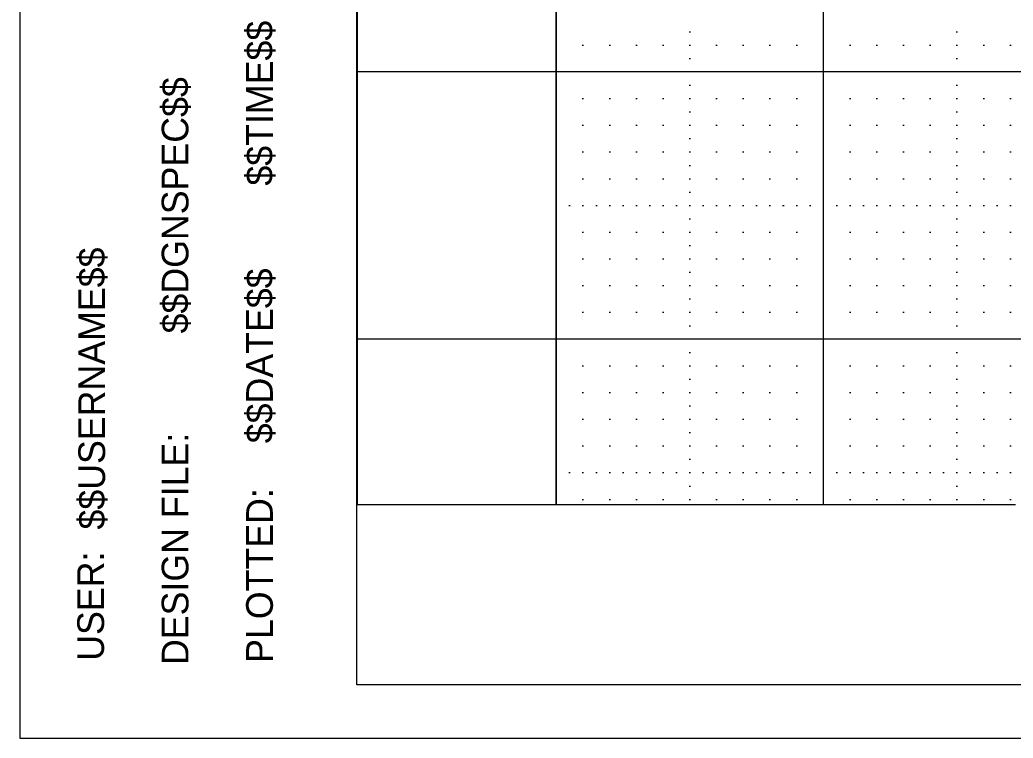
# Model space of a CAD drawing. Extents: x -1.3 to 32.1, y -0.2 to 20.7.
# Drawn here: x -1.263 to 2.455, y -0.2 to 2.487 of the extents above; entities that cross this region are included whole.
import ezdxf

# ---------------------------------------------------------------- set-up
doc = ezdxf.new("R2010")
doc.units = 0
for name, color, linetype in [('Level 1', 7, 'Continuous'), ('Level 37', 7, 'Continuous'), ('Level 4', 7, 'Continuous'), ('Level 5', 7, 'Continuous'), ('Level 62', 7, 'Continuous'), ('Level 63', 7, 'Continuous')]:
    doc.layers.add(name, color=color, linetype=linetype)

msp = doc.modelspace()

# ---------------------------------------------------------------- linework, layer by layer
at = {"layer": 'Level 1'}
for p, q in [((-0.001, -0.001), (-0.001, 20.545)), ((31.617, -0.001), (-0.001, -0.001))]:
    msp.add_line(p, q, dxfattribs=at)
at = {"layer": 'Level 37'}
for p, q in [((0.746, 0.6725), (0.746, 10.2935)), ((2.464, 0.6725), (0.746, 0.6725))]:
    msp.add_line(p, q, dxfattribs=at)
at = {"layer": 'Level 4'}
for p, q in [((0.745, 0.672), (0.745, 10.293)), ((1.745, 0.672), (1.745, 10.293)), ((31.617, 2.293), (-0.001, 2.293)), ((31.617, 1.293), (-0.001, 1.293))]:
    msp.add_line(p, q, dxfattribs=at)
at = {"layer": 'Level 5'}
for p, q in [((1.2425, 2.443), (1.2475, 2.443)), ((2.2425, 2.443), (2.2475, 2.443)), ((0.8425, 2.393), (0.8475, 2.393)), ((0.9425, 2.393), (0.9475, 2.393)), ((1.0425, 2.393), (1.0475, 2.393)), ((1.1425, 2.393), (1.1475, 2.393)), ((1.2425, 2.393), (1.2475, 2.393)), ((1.3425, 2.393), (1.3475, 2.393)), ((1.4425, 2.393), (1.4475, 2.393)), ((1.5425, 2.393), (1.5475, 2.393)), ((1.6425, 2.393), (1.6475, 2.393)), ((1.8425, 2.393), (1.8475, 2.393)), ((1.9425, 2.393), (1.9475, 2.393)), ((2.0425, 2.393), (2.0475, 2.393)), ((2.1425, 2.393), (2.1475, 2.393)), ((2.2425, 2.393), (2.2475, 2.393)), ((2.3425, 2.393), (2.3475, 2.393)), ((2.4425, 2.393), (2.4475, 2.393)), ((1.2425, 2.343), (1.2475, 2.343)), ((2.2425, 2.343), (2.2475, 2.343)), ((1.2425, 2.243), (1.2475, 2.243)), ((2.2425, 2.243), (2.2475, 2.243)), ((0.8425, 2.193), (0.8475, 2.193)), ((0.9425, 2.193), (0.9475, 2.193)), ((1.0425, 2.193), (1.0475, 2.193)), ((1.1425, 2.193), (1.1475, 2.193)), ((1.2425, 2.193), (1.2475, 2.193)), ((1.3425, 2.193), (1.3475, 2.193)), ((1.4425, 2.193), (1.4475, 2.193)), ((1.5425, 2.193), (1.5475, 2.193)), ((1.6425, 2.193), (1.6475, 2.193)), ((1.8425, 2.193), (1.8475, 2.193)), ((1.9425, 2.193), (1.9475, 2.193)), ((2.0425, 2.193), (2.0475, 2.193)), ((2.1425, 2.193), (2.1475, 2.193)), ((2.2425, 2.193), (2.2475, 2.193)), ((2.3425, 2.193), (2.3475, 2.193)), ((2.4425, 2.193), (2.4475, 2.193)), ((1.2425, 2.143), (1.2475, 2.143)), ((2.2425, 2.143), (2.2475, 2.143)), ((0.8425, 2.093), (0.8475, 2.093)), ((0.9425, 2.093), (0.9475, 2.093)), ((1.0425, 2.093), (1.0475, 2.093)), ((1.1425, 2.093), (1.1475, 2.093)), ((1.2425, 2.093), (1.2475, 2.093)), ((1.3425, 2.093), (1.3475, 2.093)), ((1.4425, 2.093), (1.4475, 2.093)), ((1.5425, 2.093), (1.5475, 2.093)), ((1.6425, 2.093), (1.6475, 2.093)), ((1.8425, 2.093), (1.8475, 2.093)), ((1.9425, 2.093), (1.9475, 2.093)), ((2.0425, 2.093), (2.0475, 2.093)), ((2.1425, 2.093), (2.1475, 2.093)), ((2.2425, 2.093), (2.2475, 2.093)), ((2.3425, 2.093), (2.3475, 2.093)), ((2.4425, 2.093), (2.4475, 2.093)), ((1.2425, 2.043), (1.2475, 2.043)), ((2.2425, 2.043), (2.2475, 2.043)), ((0.8425, 1.993), (0.8475, 1.993)), ((0.9425, 1.993), (0.9475, 1.993)), ((1.0425, 1.993), (1.0475, 1.993)), ((1.1425, 1.993), (1.1475, 1.993)), ((1.2425, 1.993), (1.2475, 1.993)), ((1.3425, 1.993), (1.3475, 1.993)), ((1.4425, 1.993), (1.4475, 1.993)), ((1.5425, 1.993), (1.5475, 1.993)), ((1.6425, 1.993), (1.6475, 1.993)), ((1.8425, 1.993), (1.8475, 1.993)), ((1.9425, 1.993), (1.9475, 1.993)), ((2.0425, 1.993), (2.0475, 1.993)), ((2.1425, 1.993), (2.1475, 1.993)), ((2.2425, 1.993), (2.2475, 1.993)), ((2.3425, 1.993), (2.3475, 1.993)), ((2.4425, 1.993), (2.4475, 1.993)), ((1.2425, 1.943), (1.2475, 1.943)), ((2.2425, 1.943), (2.2475, 1.943)), ((0.8425, 1.893), (0.8475, 1.893)), ((0.9425, 1.893), (0.9475, 1.893)), ((1.0425, 1.893), (1.0475, 1.893)), ((1.1425, 1.893), (1.1475, 1.893)), ((1.2425, 1.893), (1.2475, 1.893)), ((1.3425, 1.893), (1.3475, 1.893)), ((1.4425, 1.893), (1.4475, 1.893)), ((1.5425, 1.893), (1.5475, 1.893)), ((1.6425, 1.893), (1.6475, 1.893)), ((1.8425, 1.893), (1.8475, 1.893)), ((1.9425, 1.893), (1.9475, 1.893)), ((2.0425, 1.893), (2.0475, 1.893)), ((2.1425, 1.893), (2.1475, 1.893)), ((2.2425, 1.893), (2.2475, 1.893)), ((2.3425, 1.893), (2.3475, 1.893)), ((2.4425, 1.893), (2.4475, 1.893)), ((1.2425, 1.843), (1.2475, 1.843)), ((2.2425, 1.843), (2.2475, 1.843)), ((0.7925, 1.793), (0.7975, 1.793)), ((0.8425, 1.793), (0.8475, 1.793)), ((0.8925, 1.793), (0.8975, 1.793)), ((0.9425, 1.793), (0.9475, 1.793)), ((0.9925, 1.793), (0.9975, 1.793)), ((1.0425, 1.793), (1.0475, 1.793)), ((1.0925, 1.793), (1.0975, 1.793)), ((1.1425, 1.793), (1.1475, 1.793)), ((1.1925, 1.793), (1.1975, 1.793)), ((1.2425, 1.793), (1.2475, 1.793)), ((1.2925, 1.793), (1.2975, 1.793)), ((1.3425, 1.793), (1.3475, 1.793)), ((1.3925, 1.793), (1.3975, 1.793)), ((1.4425, 1.793), (1.4475, 1.793)), ((1.4925, 1.793), (1.4975, 1.793)), ((1.5425, 1.793), (1.5475, 1.793)), ((1.5925, 1.793), (1.5975, 1.793)), ((1.6425, 1.793), (1.6475, 1.793)), ((1.6925, 1.793), (1.6975, 1.793)), ((1.7925, 1.793), (1.7975, 1.793)), ((1.8425, 1.793), (1.8475, 1.793)), ((1.8925, 1.793), (1.8975, 1.793)), ((1.9425, 1.793), (1.9475, 1.793)), ((1.9925, 1.793), (1.9975, 1.793)), ((2.0425, 1.793), (2.0475, 1.793)), ((2.0925, 1.793), (2.0975, 1.793)), ((2.1425, 1.793), (2.1475, 1.793)), ((2.1925, 1.793), (2.1975, 1.793)), ((2.2425, 1.793), (2.2475, 1.793)), ((2.2925, 1.793), (2.2975, 1.793)), ((2.3425, 1.793), (2.3475, 1.793)), ((2.3925, 1.793), (2.3975, 1.793)), ((2.4425, 1.793), (2.4475, 1.793)), ((1.2425, 1.743), (1.2475, 1.743)), ((2.2425, 1.743), (2.2475, 1.743)), ((0.8425, 1.693), (0.8475, 1.693)), ((0.9425, 1.693), (0.9475, 1.693)), ((1.0425, 1.693), (1.0475, 1.693)), ((1.1425, 1.693), (1.1475, 1.693)), ((1.2425, 1.693), (1.2475, 1.693)), ((1.3425, 1.693), (1.3475, 1.693)), ((1.4425, 1.693), (1.4475, 1.693)), ((1.5425, 1.693), (1.5475, 1.693)), ((1.6425, 1.693), (1.6475, 1.693)), ((1.8425, 1.693), (1.8475, 1.693)), ((1.9425, 1.693), (1.9475, 1.693)), ((2.0425, 1.693), (2.0475, 1.693)), ((2.1425, 1.693), (2.1475, 1.693)), ((2.2425, 1.693), (2.2475, 1.693)), ((2.3425, 1.693), (2.3475, 1.693)), ((2.4425, 1.693), (2.4475, 1.693)), ((1.2425, 1.643), (1.2475, 1.643)), ((2.2425, 1.643), (2.2475, 1.643)), ((0.8425, 1.593), (0.8475, 1.593)), ((0.9425, 1.593), (0.9475, 1.593)), ((1.0425, 1.593), (1.0475, 1.593)), ((1.1425, 1.593), (1.1475, 1.593)), ((1.2425, 1.593), (1.2475, 1.593)), ((1.3425, 1.593), (1.3475, 1.593)), ((1.4425, 1.593), (1.4475, 1.593)), ((1.5425, 1.593), (1.5475, 1.593)), ((1.6425, 1.593), (1.6475, 1.593)), ((1.8425, 1.593), (1.8475, 1.593)), ((1.9425, 1.593), (1.9475, 1.593)), ((2.0425, 1.593), (2.0475, 1.593)), ((2.1425, 1.593), (2.1475, 1.593)), ((2.2425, 1.593), (2.2475, 1.593)), ((2.3425, 1.593), (2.3475, 1.593)), ((2.4425, 1.593), (2.4475, 1.593)), ((1.2425, 1.543), (1.2475, 1.543)), ((2.2425, 1.543), (2.2475, 1.543)), ((0.8425, 1.493), (0.8475, 1.493)), ((0.9425, 1.493), (0.9475, 1.493)), ((1.0425, 1.493), (1.0475, 1.493)), ((1.1425, 1.493), (1.1475, 1.493)), ((1.2425, 1.493), (1.2475, 1.493)), ((1.3425, 1.493), (1.3475, 1.493)), ((1.4425, 1.493), (1.4475, 1.493)), ((1.5425, 1.493), (1.5475, 1.493)), ((1.6425, 1.493), (1.6475, 1.493)), ((1.8425, 1.493), (1.8475, 1.493)), ((1.9425, 1.493), (1.9475, 1.493)), ((2.0425, 1.493), (2.0475, 1.493)), ((2.1425, 1.493), (2.1475, 1.493)), ((2.2425, 1.493), (2.2475, 1.493)), ((2.3425, 1.493), (2.3475, 1.493)), ((2.4425, 1.493), (2.4475, 1.493)), ((1.2425, 1.443), (1.2475, 1.443)), ((2.2425, 1.443), (2.2475, 1.443)), ((0.8425, 1.393), (0.8475, 1.393)), ((0.9425, 1.393), (0.9475, 1.393)), ((1.0425, 1.393), (1.0475, 1.393)), ((1.1425, 1.393), (1.1475, 1.393)), ((1.2425, 1.393), (1.2475, 1.393)), ((1.3425, 1.393), (1.3475, 1.393)), ((1.4425, 1.393), (1.4475, 1.393)), ((1.5425, 1.393), (1.5475, 1.393)), ((1.6425, 1.393), (1.6475, 1.393)), ((1.8425, 1.393), (1.8475, 1.393)), ((1.9425, 1.393), (1.9475, 1.393)), ((2.0425, 1.393), (2.0475, 1.393)), ((2.1425, 1.393), (2.1475, 1.393)), ((2.2425, 1.393), (2.2475, 1.393)), ((2.3425, 1.393), (2.3475, 1.393)), ((2.4425, 1.393), (2.4475, 1.393)), ((1.2425, 1.343), (1.2475, 1.343)), ((2.2425, 1.343), (2.2475, 1.343)), ((1.2425, 1.243), (1.2475, 1.243)), ((2.2425, 1.243), (2.2475, 1.243)), ((0.8425, 1.193), (0.8475, 1.193)), ((0.9425, 1.193), (0.9475, 1.193)), ((1.0425, 1.193), (1.0475, 1.193)), ((1.1425, 1.193), (1.1475, 1.193)), ((1.2425, 1.193), (1.2475, 1.193)), ((1.3425, 1.193), (1.3475, 1.193)), ((1.4425, 1.193), (1.4475, 1.193)), ((1.5425, 1.193), (1.5475, 1.193)), ((1.6425, 1.193), (1.6475, 1.193)), ((1.8425, 1.193), (1.8475, 1.193)), ((1.9425, 1.193), (1.9475, 1.193)), ((2.0425, 1.193), (2.0475, 1.193)), ((2.1425, 1.193), (2.1475, 1.193)), ((2.2425, 1.193), (2.2475, 1.193)), ((2.3425, 1.193), (2.3475, 1.193)), ((2.4425, 1.193), (2.4475, 1.193)), ((1.2425, 1.143), (1.2475, 1.143)), ((2.2425, 1.143), (2.2475, 1.143)), ((0.8425, 1.093), (0.8475, 1.093)), ((0.9425, 1.093), (0.9475, 1.093)), ((1.0425, 1.093), (1.0475, 1.093)), ((1.1425, 1.093), (1.1475, 1.093)), ((1.2425, 1.093), (1.2475, 1.093)), ((1.3425, 1.093), (1.3475, 1.093)), ((1.4425, 1.093), (1.4475, 1.093)), ((1.5425, 1.093), (1.5475, 1.093)), ((1.6425, 1.093), (1.6475, 1.093)), ((1.8425, 1.093), (1.8475, 1.093)), ((1.9425, 1.093), (1.9475, 1.093)), ((2.0425, 1.093), (2.0475, 1.093)), ((2.1425, 1.093), (2.1475, 1.093)), ((2.2425, 1.093), (2.2475, 1.093)), ((2.3425, 1.093), (2.3475, 1.093)), ((2.4425, 1.093), (2.4475, 1.093)), ((1.2425, 1.043), (1.2475, 1.043)), ((2.2425, 1.043), (2.2475, 1.043)), ((0.8425, 0.993), (0.8475, 0.993)), ((0.9425, 0.993), (0.9475, 0.993)), ((1.0425, 0.993), (1.0475, 0.993)), ((1.1425, 0.993), (1.1475, 0.993)), ((1.2425, 0.993), (1.2475, 0.993)), ((1.3425, 0.993), (1.3475, 0.993)), ((1.4425, 0.993), (1.4475, 0.993)), ((1.5425, 0.993), (1.5475, 0.993)), ((1.6425, 0.993), (1.6475, 0.993)), ((1.8425, 0.993), (1.8475, 0.993)), ((1.9425, 0.993), (1.9475, 0.993)), ((2.0425, 0.993), (2.0475, 0.993)), ((2.1425, 0.993), (2.1475, 0.993)), ((2.2425, 0.993), (2.2475, 0.993)), ((2.3425, 0.993), (2.3475, 0.993)), ((2.4425, 0.993), (2.4475, 0.993)), ((1.2425, 0.943), (1.2475, 0.943)), ((2.2425, 0.943), (2.2475, 0.943)), ((0.8425, 0.893), (0.8475, 0.893)), ((0.9425, 0.893), (0.9475, 0.893)), ((1.0425, 0.893), (1.0475, 0.893)), ((1.1425, 0.893), (1.1475, 0.893)), ((1.2425, 0.893), (1.2475, 0.893)), ((1.3425, 0.893), (1.3475, 0.893)), ((1.4425, 0.893), (1.4475, 0.893)), ((1.5425, 0.893), (1.5475, 0.893)), ((1.6425, 0.893), (1.6475, 0.893)), ((1.8425, 0.893), (1.8475, 0.893)), ((1.9425, 0.893), (1.9475, 0.893)), ((2.0425, 0.893), (2.0475, 0.893)), ((2.1425, 0.893), (2.1475, 0.893)), ((2.2425, 0.893), (2.2475, 0.893)), ((2.3425, 0.893), (2.3475, 0.893)), ((2.4425, 0.893), (2.4475, 0.893)), ((1.2425, 0.843), (1.2475, 0.843)), ((2.2425, 0.843), (2.2475, 0.843)), ((0.7925, 0.793), (0.7975, 0.793)), ((0.8425, 0.793), (0.8475, 0.793)), ((0.8925, 0.793), (0.8975, 0.793)), ((0.9425, 0.793), (0.9475, 0.793)), ((0.9925, 0.793), (0.9975, 0.793)), ((1.0425, 0.793), (1.0475, 0.793)), ((1.0925, 0.793), (1.0975, 0.793)), ((1.1425, 0.793), (1.1475, 0.793)), ((1.1925, 0.793), (1.1975, 0.793)), ((1.2425, 0.793), (1.2475, 0.793)), ((1.2925, 0.793), (1.2975, 0.793)), ((1.3425, 0.793), (1.3475, 0.793)), ((1.3925, 0.793), (1.3975, 0.793)), ((1.4425, 0.793), (1.4475, 0.793)), ((1.4925, 0.793), (1.4975, 0.793)), ((1.5425, 0.793), (1.5475, 0.793)), ((1.5925, 0.793), (1.5975, 0.793)), ((1.6425, 0.793), (1.6475, 0.793)), ((1.6925, 0.793), (1.6975, 0.793)), ((1.7925, 0.793), (1.7975, 0.793)), ((1.8425, 0.793), (1.8475, 0.793)), ((1.8925, 0.793), (1.8975, 0.793)), ((1.9425, 0.793), (1.9475, 0.793)), ((1.9925, 0.793), (1.9975, 0.793)), ((2.0425, 0.793), (2.0475, 0.793)), ((2.0925, 0.793), (2.0975, 0.793)), ((2.1425, 0.793), (2.1475, 0.793)), ((2.1925, 0.793), (2.1975, 0.793)), ((2.2425, 0.793), (2.2475, 0.793)), ((2.2925, 0.793), (2.2975, 0.793)), ((2.3425, 0.793), (2.3475, 0.793)), ((2.3925, 0.793), (2.3975, 0.793)), ((2.4425, 0.793), (2.4475, 0.793)), ((1.2425, 0.743), (1.2475, 0.743)), ((2.2425, 0.743), (2.2475, 0.743)), ((0.8425, 0.693), (0.8475, 0.693)), ((0.9425, 0.693), (0.9475, 0.693)), ((1.0425, 0.693), (1.0475, 0.693)), ((1.1425, 0.693), (1.1475, 0.693)), ((1.2425, 0.693), (1.2475, 0.693)), ((1.3425, 0.693), (1.3475, 0.693)), ((1.4425, 0.693), (1.4475, 0.693)), ((1.5425, 0.693), (1.5475, 0.693)), ((1.6425, 0.693), (1.6475, 0.693)), ((1.8425, 0.693), (1.8475, 0.693)), ((1.9425, 0.693), (1.9475, 0.693)), ((2.0425, 0.693), (2.0475, 0.693)), ((2.1425, 0.693), (2.1475, 0.693)), ((2.2425, 0.693), (2.2475, 0.693)), ((2.3425, 0.693), (2.3475, 0.693)), ((2.4425, 0.693), (2.4475, 0.693))]:
    msp.add_line(p, q, dxfattribs=at)
at = {"layer": 'Level 62'}
for p, q in [((0, 10.294), (0, 0.6734)), ((0, 0.6734), (2.4642, 0.6734))]:
    msp.add_line(p, q, dxfattribs=at)
at = {"layer": 'Level 63'}
msp.add_lwpolyline([(-1.263, -0.2005), (32.067, -0.2005), (32.067, 20.7465), (-1.263, 20.7465)], close=True, dxfattribs=at)

# ---------------------------------------------------------------- texts
at = {"layer": 'Level 1'}
for s, height, p in [('$$TIME$$', 0.1, (-0.316, 1.867)), ('$$DGNSPEC$$', 0.100002, (-0.632, 1.314)), ('$$USERNAME$$', 0.100002, (-0.944, 0.58)), ('$$DATE$$', 0.1, (-0.316, 0.903)), ('DESIGN FILE:', 0.100002, (-0.632, 0.073)), ('PLOTTED:', 0.1, (-0.316, 0.081)), ('USER:', 0.1, (-0.948, 0.089))]:
    msp.add_text(s, height=height, rotation=90, dxfattribs=at).set_placement(p)

doc.saveas('drawing.dxf')
